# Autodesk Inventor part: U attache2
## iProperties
Created: 2002-09
Part Number: U attache2
Material: Par défaut
Document SubType Name: Modélisation
Designer: Maison
Control State: 0
Master: False
Checked Out: False
Shininess: 53.0
Length Units: 11269
Angle Units: 11279
Time Units: 11290
Mass Units: 11283
Length Display Precision: 3
Angle Display Precision: 2
Density: 0.0
Volumn: 0.0
Area: 0.0
PropertySet Name: Model Information
Author: Maison
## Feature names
1. Extrusion1
2. Extrusion2
3. Congé1 [Fillet]
4. Congé2 [Fillet]
5. Congé3 [Fillet]
